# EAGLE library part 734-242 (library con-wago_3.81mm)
Serie 734, Stiftleiste (für Leiterplatten) Einlötstift gerade 1 x 1 mm / Series 734, Male header (for PCBs) Straight solder pin 1 x 1 mm Polzahl / Pole No.: 12 Rastermaß / Pitch: 3.81 mm Bemessungsspannung / Rated Voltage: 160 V Nennstrom / Nominal Current: 10 A Lötstiftlänge: / Solder Pin Length: 4.5 mm Farbe / Color: orange / orange Stand: 01.01.2012. Die jeweils aktuellen Daten zu diesem Artikel finden Sie in unserem Produktkatalog, den Sie unter www.wago.com einsehen können. As of: 01/01/2012. Please find the newest data for this article in our product catalogue, which can be viewed under www.wago.com.
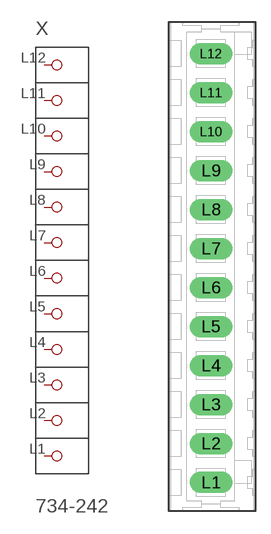
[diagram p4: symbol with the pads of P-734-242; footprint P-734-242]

Designator prefix X

## 734-242  [P-734-242]
L1  P1
L2  P2
L3  P3
L4  P4
L5  P5
L6  P6
L7  P7
L8  P8
L9  P9
L10  P10
L11  P11
L12  P12

## Footprint P-734-242 (pad centres in mm)
drill 1.4 long: L1 -0.1,-21.105; L2 -0.1,-17.295; L3 -0.1,-13.485; L4 -0.1,-9.675; L5 -0.1,-5.865; L6 -0.1,-2.055; L7 -0.1,1.755; L8 -0.1,5.565; L9 -0.1,9.375; L10 -0.1,13.185; L11 -0.1,16.995; L12 -0.1,20.805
